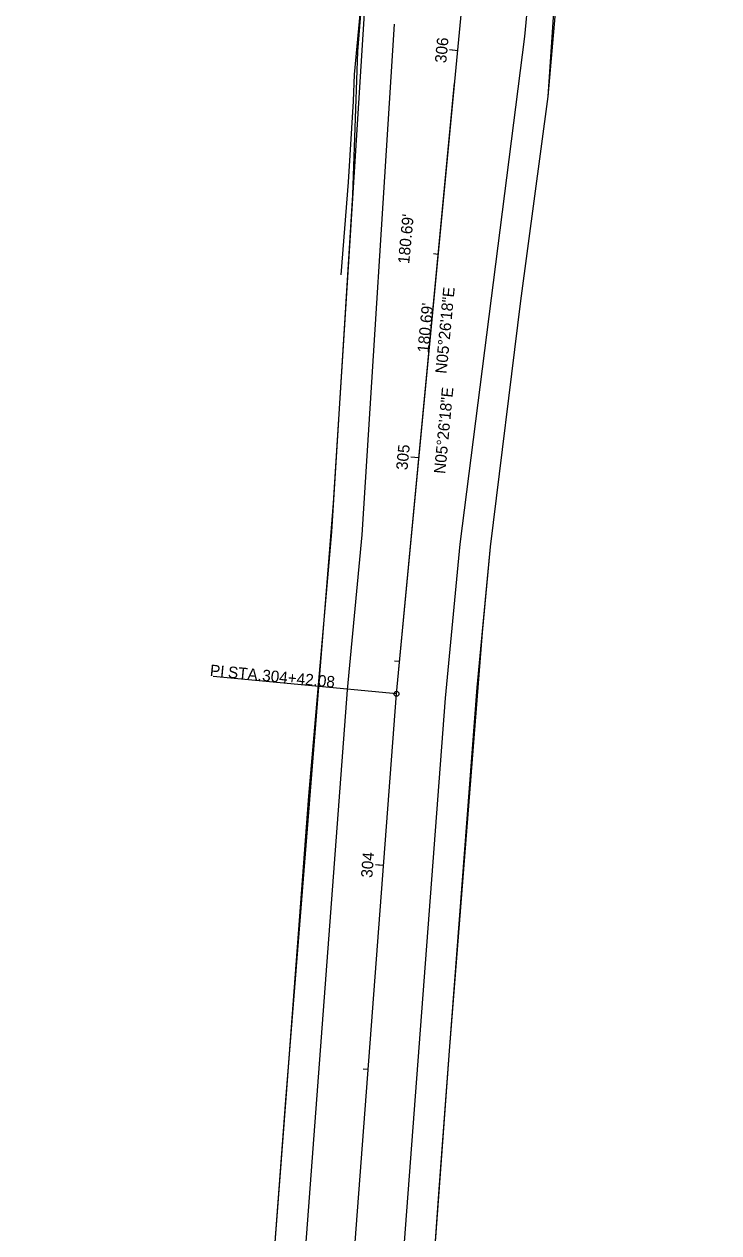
# Model space of a CAD drawing. Extents: x 219353 to 221640, y 361458 to 364236.
# Drawn here: x 220461.9 to 220631.7, y 361769.6 to 362065.1 of the extents above; entities that cross this region are included whole.
import ezdxf

# ---------------------------------------------------------------- set-up
doc = ezdxf.new("R2010")
doc.units = 0
for name, color, linetype in [('Default', 7, 'Continuous'), ('DR_P_Cells', 7, 'Continuous'), ('DR_P_GenericNode', 7, 'Continuous'), ('DR_X_Cells', 7, 'Continuous'), ('DR_X_GenericNode', 7, 'Continuous'), ('DT_X_Contour_Major', 7, 'Continuous'), ('DT_X_Contour_Minor', 7, 'Continuous'), ('SC_ProfileRun1', 7, 'Continuous'), ('SC_ProfileRun2', 7, 'Continuous'), ('SC_ProfileRun3', 7, 'Continuous'), ('SC_Scratch1', 7, 'Continuous'), ('UT_X_Sanitary_Cells', 7, 'Continuous')]:
    doc.layers.add(name, color=color, linetype=linetype)

msp = doc.modelspace()

# ---------------------------------------------------------------- linework, layer by layer
at = {"layer": 'Default'}
for p, q in [((220589.94, 362047.45), (220608.12, 362317.78)), ((220583.28, 361997.5), (220589.94, 362047.45)), ((220575.89, 361937.29), (220583.28, 361997.5)), ((220573.9, 361916.38), (220575.89, 361937.29)), ((220565.88, 361814.09), (220573.9, 361916.38)), ((220563.26, 361779.19), (220565.88, 361814.09)), ((220558.36, 361711.68), (220563.26, 361779.19))]:
    msp.add_line(p, q, dxfattribs=at)
at = {"layer": 'DR_X_Cells'}
msp.add_line((220552.88, 361901.39), (220508.08, 361905.66), dxfattribs=at)
msp.add_circle((220552.88, 361901.39), 0.6, dxfattribs=at)
at = {"layer": 'DR_X_GenericNode'}
for p, q in [((220541.47, 362010.88), (220631.67, 363446.41)), ((220589.94, 362047.45), (220595.41, 362110.45)), ((220543.46, 362058.41), (220547.06, 362103.67)), ((220584.25, 362062.06), (220585.93, 362079.75)), ((220544.53, 361940.28), (220552.39, 362065.09)), ((220568.42, 361938), (220584.25, 362062.06)), ((220542.25, 362023.37), (220543.46, 362058.41)), ((220583.28, 361997.5), (220589.94, 362047.45)), ((220537.06, 361940.99), (220542.25, 362023.37)), ((220537.5, 361947.98), (220541.47, 362010.88)), ((220575.89, 361937.29), (220583.28, 361997.5)), ((220525.87, 361802.05), (220537.5, 361947.98)), ((220531.45, 361876.34), (220537.06, 361940.99)), ((220540.92, 361902.41), (220544.53, 361940.28)), ((220564.84, 361900.37), (220568.42, 361938)), ((220572.62, 361902.95), (220575.89, 361937.29)), ((220517.55, 361591.08), (220540.92, 361902.41)), ((220565.88, 361814.09), (220572.62, 361902.95)), ((220541.36, 361587.55), (220564.84, 361900.37)), ((220525.91, 361802.55), (220531.45, 361876.34)), ((220563.3, 361779.69), (220565.88, 361814.09)), ((220510.07, 361591.64), (220525.91, 361802.55)), ((220510.08, 361591.64), (220525.87, 361802.05)), ((220558.36, 361711.68), (220563.3, 361779.69))]:
    msp.add_line(p, q, dxfattribs=at)
at = {"layer": 'DT_X_Contour_Major'}
for p, q in [((220552.88, 361901.39), (220570.01, 362081.26)), ((220552.88, 361901.39), (220567.1, 362050.75)), ((220519.79, 361460.55), (220552.88, 361901.39))]:
    msp.add_line(p, q, dxfattribs=at)
at = {"layer": 'DT_X_Contour_Minor'}
for p, q in [((220584.25, 362062.06), (220585.93, 362079.75)), ((220584.25, 362062.06), (220585.93, 362079.75)), ((220584.25, 362062.06), (220585.93, 362079.75)), ((220584.25, 362062.06), (220585.93, 362079.75)), ((220544.53, 361940.28), (220552.39, 362065.09)), ((220544.53, 361940.28), (220552.39, 362065.09)), ((220544.53, 361940.28), (220552.39, 362065.09)), ((220544.53, 361940.28), (220552.39, 362065.09)), ((220568.42, 361938), (220584.25, 362062.06)), ((220568.42, 361938), (220584.25, 362062.06)), ((220568.42, 361938), (220584.25, 362062.06)), ((220568.42, 361938), (220584.25, 362062.06)), ((220540.92, 361902.41), (220544.53, 361940.28)), ((220540.92, 361902.41), (220544.53, 361940.28)), ((220540.92, 361902.41), (220544.53, 361940.28)), ((220540.92, 361902.41), (220544.53, 361940.28)), ((220564.84, 361900.37), (220568.42, 361938)), ((220564.84, 361900.37), (220568.42, 361938)), ((220564.84, 361900.37), (220568.42, 361938)), ((220564.84, 361900.37), (220568.42, 361938)), ((220516.05, 361571.09), (220540.92, 361902.41)), ((220516.05, 361571.09), (220540.92, 361902.41)), ((220517.55, 361591.08), (220540.92, 361902.41)), ((220517.55, 361591.08), (220540.92, 361902.41)), ((220539.99, 361569.29), (220564.84, 361900.37)), ((220539.99, 361569.29), (220564.84, 361900.37)), ((220541.52, 361589.77), (220564.84, 361900.37)), ((220541.52, 361589.77), (220564.84, 361900.37))]:
    msp.add_line(p, q, dxfattribs=at)
for points in [[(220542.63, 362052.8), (220544.35, 362071.05), (220545.67, 362089.98), (220547.11, 362109.41), (220545.79, 362110.48), (220540.64, 362115.08), (220539.5, 362116.23), (220525.19, 362113.93), (220504.07, 362110.45), (220488.27, 362107.93), (220480.39, 362108.46), (220472.41, 362109.12), (220464.36, 362109.73), (220463.61, 362104.26), (220462.9, 362098.83), (220461.92, 362080.65)], [(220539.36, 362003.82), (220541.17, 362026.46), (220542.4, 362046.24), (220542.63, 362052.8)]]:
    msp.add_lwpolyline(points, dxfattribs=at)
at = {"layer": 'SC_ProfileRun2'}
msp.add_line((220552.88, 361901.39), (220508.08, 361905.66), dxfattribs=at)
msp.add_circle((220552.88, 361901.39), 0.6, dxfattribs=at)
at = {"layer": 'SC_ProfileRun3'}
for p, q in [((220567.85, 362058.6), (220566.65, 362058.71)), ((220558.37, 361959.05), (220556.38, 361959.24)), ((220549.73, 361859.43), (220548.53, 361859.52))]:
    msp.add_line(p, q, dxfattribs=at)
at = {"layer": 'UT_X_Sanitary_Cells'}
for p, q in [((220567.85, 362058.6), (220565.86, 362058.79)), ((220563.11, 362008.82), (220561.91, 362008.94)), ((220558.37, 361959.05), (220556.38, 361959.24)), ((220553.63, 361909.27), (220552.44, 361909.39)), ((220549.73, 361859.43), (220547.74, 361859.58)), ((220545.99, 361809.57), (220544.79, 361809.66))]:
    msp.add_line(p, q, dxfattribs=at)

# ---------------------------------------------------------------- texts
at = {"layer": 'DR_P_Cells'}
msp.add_text("180.69'", height=2.8, rotation=84.5615, dxfattribs=at).set_placement((220560.77, 361984.68))
at = {"layer": 'DR_P_GenericNode'}
msp.add_text("180.69'", height=2.8, rotation=84.5615, dxfattribs=at).set_placement((220556, 362006.41))
at = {"layer": 'DR_X_Cells'}
for s, p in [('PI', (220507.21, 361905.78)), (' STA. ', (220510.58, 361905.46)), ('304+42.08', (220519.99, 361904.56))]:
    msp.add_text(s, height=2.8, rotation=354.5615, dxfattribs=at).set_placement(p)
at = {"layer": 'SC_ProfileRun1'}
msp.add_text('N05°26\'18"E', height=2.8, rotation=84.5615, dxfattribs=at).set_placement((220564.81, 361955.08))
at = {"layer": 'SC_ProfileRun2'}
for s, p in [('PI', (220507.21, 361905.78)), (' STA. ', (220510.58, 361905.46)), ('304+42.08', (220519.99, 361904.56))]:
    msp.add_text(s, height=2.8, rotation=354.5615, dxfattribs=at).set_placement(p)
at = {"layer": 'SC_ProfileRun3'}
msp.add_text('305', height=2.8, rotation=84.5615, dxfattribs=at).set_placement((220555.57, 361956))
at = {"layer": 'SC_Scratch1'}
msp.add_text('N05°26\'18"E', height=2.8, rotation=84.5615, dxfattribs=at).set_placement((220565.14, 361979.56))
at = {"layer": 'UT_X_Sanitary_Cells'}
for s, rotation, p in [('306', 84.5615, (220565.04, 362055.49)), ('305', 84.5615, (220555.57, 361956)), ('304', 85.7073, (220546.99, 361856.35))]:
    msp.add_text(s, height=2.8, rotation=rotation, dxfattribs=at).set_placement(p)

doc.saveas('drawing.dxf')
